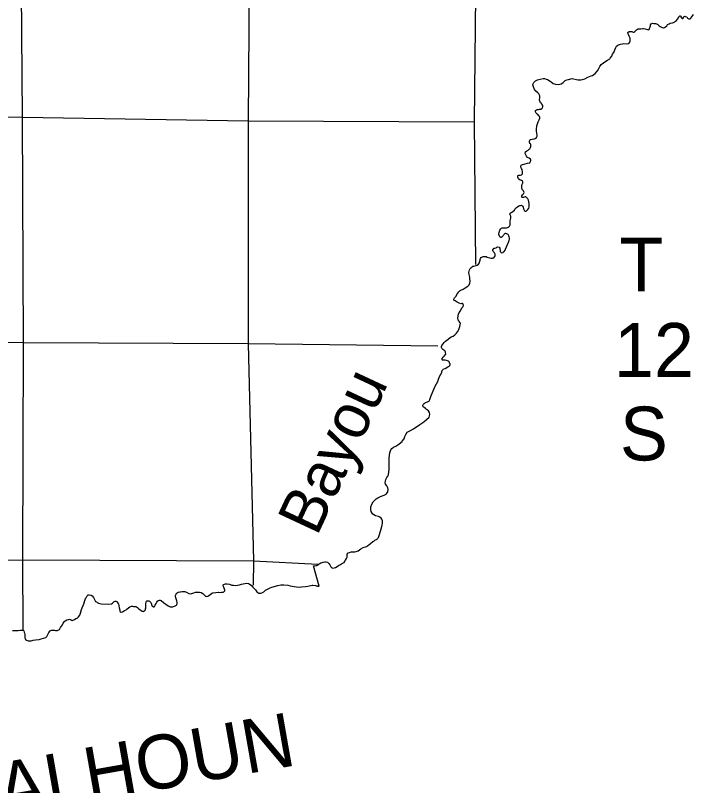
# Model space of a CAD drawing. Extents: x 369523 to 838377, y 495025 to 936819.
# Drawn here: x 707170 to 723147, y 607625 to 625753 of the extents above; entities that cross this region are included whole.
import ezdxf

# ---------------------------------------------------------------- set-up
doc = ezdxf.new("R2010")
doc.units = 0
for name, color, linetype in [('21', 7, 'Continuous'), ('Level 10', 7, 'Continuous'), ('Level 22', 7, 'Continuous'), ('Level 6', 7, 'Continuous')]:
    doc.layers.add(name, color=color, linetype=linetype)

msp = doc.modelspace()

# ---------------------------------------------------------------- linework, layer by layer
at = {"layer": '21'}
msp.add_line((721719, 617879), (721719, 617879), dxfattribs=at)
at = {"layer": 'Level 22'}
for points in [[(717984, 632258), (718036, 628459), (717975, 623251), (718009, 619890)], [(712679, 630326), (712692, 628709), (712656, 623272), (712654, 618019), (712776, 612916), (712771, 612344)], [(707356, 611282), (707347, 612941), (707357, 618044), (707336, 623361), (707299, 628330)], [(702444, 623403), (707336, 623361), (712656, 623272), (717975, 623251)], [(717123, 617969), (712654, 618019), (707357, 618044), (702484, 618099)], [(702445, 612932), (707347, 612941), (712776, 612916), (714295, 612837)]]:
    msp.add_lwpolyline(points, dxfattribs=at)
at = {"layer": 'Level 6'}
for points in [[(722357, 625490), (722405, 625469), (722427, 625458), (722435, 625458), (722465, 625467), (722484, 625484), (722515, 625507), (722534, 625536), (722570, 625557), (722595, 625568), (722603, 625568), (722649, 625581), (722672, 625586), (722690, 625595), (722708, 625603), (722723, 625614), (722743, 625631), (722770, 625662), (722795, 625696), (722800, 625719), (722809, 625735), (722813, 625739), (722819, 625743), (722825, 625743), (722833, 625742), (722845, 625734), (722850, 625720), (722864, 625697), (722881, 625679), (722891, 625681), (722901, 625686), (722916, 625708), (722927, 625725), (722937, 625733), (722945, 625731), (722984, 625717), (723006, 625691), (723019, 625682), (723033, 625674), (723051, 625671), (723055, 625671), (723063, 625675), (723078, 625690), (723109, 625717), (723132, 625751), (723147, 625778)], [(719602, 624265), (719636, 624267), (719677, 624251), (719709, 624243), (719770, 624207), (719790, 624186), (719842, 624152), (719890, 624132), (719954, 624126), (719999, 624135), (720025, 624145), (720063, 624169), (720093, 624193), (720124, 624220), (720160, 624240), (720190, 624246), (720202, 624248), (720284, 624267), (720419, 624237), (720461, 624234), (720491, 624236), (720531, 624244), (720581, 624262), (720658, 624303), (720692, 624313), (720736, 624327), (720762, 624339), (720831, 624388), (720881, 624448), (720918, 624507), (720940, 624553), (720967, 624599), (721023, 624637), (721081, 624676), (721118, 624698), (721170, 624732), (721182, 624746), (721217, 624795), (721231, 624821), (721237, 624839), (721257, 624871), (721272, 624893), (721292, 624945), (721312, 625001), (721327, 625030), (721359, 625050), (721377, 625060), (721425, 625074), (721473, 625082), (721504, 625089), (721570, 625085), (721620, 625093), (721646, 625124), (721652, 625150), (721655, 625182), (721649, 625218), (721629, 625268), (721611, 625304), (721599, 625334), (721596, 625354), (721628, 625374), (721648, 625378), (721690, 625374), (721720, 625358), (721742, 625360), (721760, 625377), (721780, 625393), (721805, 625411), (721827, 625433), (721845, 625441), (721861, 625441), (721873, 625441), (721907, 625441), (721945, 625444), (721967, 625442), (722009, 625436), (722059, 625418), (722091, 625417), (722102, 625419), (722112, 625443), (722130, 625509), (722134, 625535), (722147, 625557), (722161, 625565), (722181, 625569), (722209, 625565), (722241, 625566), (722253, 625564), (722271, 625556), (722287, 625550), (722297, 625544), (722311, 625534), (722337, 625506), (722357, 625490)], [(719059, 621878), (719027, 621902), (719019, 621910), (719007, 621944), (719003, 621966), (719007, 621982), (719015, 621984), (719029, 621992), (719049, 621996), (719069, 621994), (719090, 621997), (719118, 622021), (719120, 622039), (719116, 622067), (719106, 622125), (719093, 622147), (719075, 622181), (719075, 622199), (719085, 622227), (719115, 622243), (719157, 622255), (719182, 622263), (719236, 622274), (719270, 622280), (719292, 622284), (719308, 622314), (719310, 622334), (719309, 622346), (719303, 622366), (719277, 622390), (719247, 622404), (719231, 622410), (719207, 622440), (719191, 622470), (719179, 622504), (719186, 622540), (719218, 622562), (719248, 622582), (719276, 622602), (719286, 622615), (719307, 622647), (719313, 622669), (719315, 622689), (719315, 622711), (719307, 622727), (719291, 622737), (719281, 622775), (719281, 622791), (719286, 622817), (719308, 622833), (719380, 622847), (719388, 622847), (719412, 622854), (719447, 622878), (719463, 622908), (719465, 622936), (719453, 622980), (719448, 623026), (719448, 623076), (719456, 623154), (719475, 623222), (719489, 623251), (719510, 623295), (719526, 623331), (719522, 623357), (719516, 623373), (719504, 623393), (719484, 623415), (719464, 623431), (719440, 623449), (719423, 623483), (719423, 623487), (719425, 623513), (719449, 623529), (719467, 623537), (719491, 623539), (719515, 623543), (719551, 623549), (719580, 623566), (719590, 623586), (719594, 623600), (719592, 623632), (719572, 623662), (719560, 623678), (719542, 623697), (719532, 623721), (719517, 623761), (719527, 623820), (719521, 623860), (719504, 623904), (719480, 623931), (719428, 623973), (719400, 624009), (719374, 624073), (719359, 624119), (719369, 624141), (719385, 624175), (719426, 624217), (719466, 624236), (719532, 624250), (719602, 624265)], [(718709, 620621), (718691, 620614), (718681, 620602), (718673, 620590), (718663, 620570), (718649, 620556), (718634, 620542), (718622, 620534), (718614, 620528), (718602, 620526), (718580, 620544), (718574, 620554), (718572, 620560), (718561, 620594), (718557, 620610), (718567, 620640), (718585, 620700), (718604, 620726), (718622, 620744), (718636, 620752), (718664, 620752), (718684, 620753), (718724, 620753), (718740, 620755), (718764, 620761), (718784, 620767), (718809, 620789), (718827, 620826), (718829, 620920), (718832, 620950), (718834, 620950), (718842, 620978), (718844, 620996), (718844, 621010), (718840, 621024), (718832, 621042), (718822, 621060), (718819, 621080), (718825, 621102), (718849, 621116), (718867, 621124), (718899, 621144), (718925, 621171), (718934, 621189), (718940, 621199), (718974, 621231), (719000, 621251), (719026, 621269), (719051, 621277), (719067, 621282), (719089, 621284), (719109, 621274), (719123, 621260), (719133, 621236), (719142, 621204), (719154, 621172), (719164, 621156), (719178, 621142), (719206, 621148), (719222, 621162), (719245, 621188), (719263, 621215), (719271, 621247), (719271, 621271), (719271, 621293), (719270, 621323), (719266, 621369), (719258, 621401), (719244, 621433), (719216, 621461), (719198, 621485), (719180, 621482), (719158, 621474), (719142, 621466), (719130, 621464), (719118, 621464), (719106, 621466), (719100, 621478), (719098, 621484), (719098, 621492), (719104, 621504), (719120, 621530), (719145, 621558), (719147, 621570), (719153, 621582), (719151, 621602), (719139, 621624), (719121, 621640), (719111, 621654), (719100, 621694), (719098, 621742), (719108, 621784), (719118, 621796), (719126, 621803), (719128, 621819), (719125, 621829), (719123, 621839), (719113, 621853), (719095, 621868), (719071, 621876), (719059, 621878)], [(717719, 618905), (717723, 618929), (717721, 618939), (717715, 618957), (717701, 618969), (717689, 618970), (717665, 618968), (717625, 618982), (717581, 619006), (717557, 619016), (717529, 619032), (717509, 619044), (717499, 619057), (717497, 619067), (717503, 619086), (717513, 619102), (717525, 619116), (717552, 619148), (717572, 619184), (717592, 619214), (717613, 619248), (717645, 619275), (717661, 619285), (717715, 619311), (717768, 619343), (717832, 619380), (717858, 619410), (717877, 619450), (717885, 619500), (717879, 619554), (717872, 619592), (717858, 619656), (717854, 619702), (717857, 619730), (717867, 619765), (717883, 619793), (717901, 619815), (717919, 619831), (717948, 619847), (717968, 619853), (718026, 619864), (718052, 619872), (718076, 619896), (718101, 619930), (718107, 619944), (718117, 619990), (718119, 620008), (718125, 620028), (718142, 620053), (718170, 620069), (718186, 620075), (718214, 620075), (718238, 620077), (718264, 620077), (718286, 620061), (718340, 620050), (718378, 620040), (718408, 620036), (718428, 620044), (718444, 620048), (718463, 620076), (718473, 620099), (718473, 620131), (718457, 620167), (718427, 620196), (718414, 620222), (718416, 620232), (718438, 620267), (718448, 620273), (718462, 620273), (718466, 620273), (718492, 620285), (718510, 620299), (718528, 620309), (718565, 620299), (718582, 620277), (718582, 620259), (718590, 620221), (718590, 620211), (718594, 620199), (718604, 620183), (718616, 620171), (718630, 620168), (718662, 620176), (718672, 620188), (718682, 620200), (718706, 620228), (718717, 620254), (718790, 620417), (718796, 620429), (718804, 620455), (718808, 620485), (718809, 620513), (718803, 620545), (718797, 620565), (718787, 620579), (718775, 620593), (718747, 620609), (718735, 620615), (718723, 620621), (718709, 620621)], [(716081, 615587), (716130, 615613), (716182, 615647), (716212, 615668), (716285, 615726), (716285, 615730), (716325, 615788), (716344, 615843), (716366, 615891), (716401, 615941), (716481, 615984), (716548, 616024), (716699, 616121), (716792, 616190), (716856, 616238), (716915, 616300), (716935, 616361), (716923, 616409), (716898, 616443), (716852, 616478), (716828, 616500), (716796, 616522), (716780, 616540), (716770, 616566), (716770, 616578), (716776, 616598), (716790, 616612), (716800, 616620), (716805, 616622), (716833, 616640), (716881, 616659), (716927, 616685), (716933, 616709), (716954, 616787), (717009, 616918), (717060, 617024), (717121, 617135), (717139, 617191), (717172, 617267), (717194, 617303), (717213, 617354), (717225, 617394), (717247, 617420), (717257, 617432), (717294, 617446), (717356, 617479), (717392, 617497), (717408, 617515), (717412, 617539), (717411, 617551), (717395, 617569), (717393, 617593), (717375, 617613), (717351, 617625), (717327, 617631), (717293, 617640), (717271, 617640), (717249, 617640), (717231, 617642), (717223, 617650), (717221, 617664), (717225, 617680), (717245, 617710), (717273, 617732), (717310, 617781), (717310, 617783), (717300, 617829), (717294, 617851), (717272, 617871), (717260, 617877), (717240, 617890), (717224, 617902), (717214, 617918), (717213, 617924), (717207, 617938), (717209, 617960), (717217, 617984), (717245, 618023), (717272, 618053), (717300, 618089), (717433, 618190), (717483, 618206), (717526, 618235), (717562, 618271), (717588, 618305), (717619, 618361), (717643, 618431), (717652, 618508), (717640, 618528), (717624, 618550), (717614, 618564), (717604, 618581), (717598, 618599), (717596, 618625), (717597, 618684), (717605, 618720), (717625, 618762), (717652, 618800), (717686, 618870), (717711, 618893), (717719, 618905)], [(714254, 612330), (714276, 612326), (714290, 612320), (714310, 612318), (714324, 612316), (714191, 612794), (714217, 612800), (714247, 612802), (714269, 612804), (714301, 612823), (714324, 612841), (714364, 612865), (714396, 612877), (714420, 612885), (714458, 612894), (714487, 612894), (714525, 612880), (714552, 612856), (714574, 612820), (714592, 612788), (714604, 612772), (714616, 612756), (714650, 612745), (714676, 612747), (714708, 612761), (714747, 612781), (714783, 612803), (714827, 612832), (714877, 612858), (714912, 612876), (714940, 612913), (714950, 612931), (714968, 612967), (714983, 613001), (714985, 613059), (714989, 613073), (715009, 613103), (715042, 613115), (715082, 613126), (715124, 613128), (715164, 613124), (715198, 613136), (715244, 613149), (715273, 613171), (715307, 613199), (715363, 613227), (715416, 613246), (715446, 613256), (715468, 613270), (715502, 613300), (715532, 613324), (715591, 613367), (715613, 613381), (715639, 613399), (715696, 613426), (715700, 613438), (715722, 613464), (715738, 613510), (715771, 613610), (715786, 613672), (715814, 613755), (715819, 613799), (715819, 613857), (715805, 613895), (715787, 613921), (715757, 613941), (715723, 613958), (715655, 613978), (715615, 613996), (715587, 614014), (715575, 614034), (715552, 614078), (715544, 614118), (715546, 614190), (715565, 614250), (715601, 614306), (715618, 614328), (715670, 614377), (715706, 614401), (715753, 614421), (715809, 614446), (715855, 614462), (715901, 614484), (715928, 614514), (715940, 614540), (715948, 614591), (715943, 614633), (715921, 614677), (715891, 614722), (715879, 614760), (715885, 614792), (715898, 614829), (715924, 614873), (715946, 614907), (715959, 614941), (715972, 615069), (715979, 615336), (715988, 615458), (716015, 615530), (716041, 615558), (716081, 615587)], [(710819, 611831), (710875, 611830), (710931, 611852), (710965, 611872), (710982, 611900), (710984, 611924), (710974, 611970), (710958, 612020), (710946, 612048), (710941, 612080), (710943, 612100), (710957, 612132), (710961, 612140), (710979, 612163), (711007, 612177), (711044, 612185), (711062, 612187), (711100, 612193), (711142, 612194), (711162, 612192), (711178, 612188), (711202, 612176), (711256, 612146), (711258, 612146), (711294, 612140), (711330, 612149), (711370, 612163), (711413, 612175), (711445, 612181), (711477, 612180), (711507, 612180), (711549, 612166), (711587, 612146), (711601, 612132), (711629, 612102), (711645, 612082), (711655, 612082), (711673, 612079), (711705, 612083), (711727, 612103), (711761, 612125), (711792, 612147), (711812, 612163), (711892, 612172), (711954, 612174), (711974, 612172), (712022, 612175), (712061, 612181), (712079, 612185), (712091, 612193), (712105, 612209), (712105, 612227), (712097, 612251), (712083, 612293), (712068, 612323), (712066, 612351), (712082, 612361), (712092, 612367), (712120, 612371), (712160, 612374), (712210, 612364), (712272, 612342), (712306, 612339), (712365, 612337), (712399, 612343), (712451, 612351), (712495, 612362), (712577, 612384), (712618, 612390), (712658, 612383), (712676, 612375), (712734, 612333), (712767, 612297), (712791, 612267), (712823, 612229), (712839, 612207), (712859, 612188), (712881, 612170), (712905, 612156), (712929, 612152), (712953, 612156), (712975, 612162), (713025, 612188), (713058, 612223), (713173, 612277), (713213, 612292), (713353, 612335), (713422, 612349), (713494, 612349), (713584, 612340), (713646, 612330), (713738, 612313), (713793, 612303), (713857, 612299), (713907, 612302), (714005, 612314), (714059, 612321), (714164, 612341), (714178, 612343), (714242, 612336), (714254, 612330)], [(708508, 611507), (708524, 611516), (708544, 611524), (708562, 611534), (708594, 611554), (708624, 611566), (708655, 611594), (708689, 611639), (708707, 611683), (708730, 611771), (708783, 611904), (708816, 612008), (708832, 612046), (708842, 612062), (708863, 612094), (708887, 612112), (708901, 612115), (708911, 612115), (708955, 612109), (708979, 612093), (709011, 612049), (709023, 612021), (709060, 611961), (709080, 611947), (709100, 611933), (709126, 611922), (709192, 611904), (709367, 611893), (709433, 611905), (709457, 611917), (709473, 611936), (709494, 611956), (709518, 611964), (709536, 611962), (709558, 611956), (709570, 611944), (709586, 611922), (709595, 611900), (709607, 611856), (709613, 611810), (709619, 611786), (709623, 611774), (709627, 611752), (709632, 611732), (709638, 611714), (709654, 611706), (709664, 611704), (709690, 611715), (709739, 611743), (709777, 611763), (709805, 611787), (709868, 611836), (709908, 611846), (709928, 611846), (709954, 611844), (709978, 611842), (710008, 611839), (710026, 611833), (710046, 611815), (710076, 611789), (710110, 611765), (710160, 611733), (710176, 611727), (710194, 611725), (710212, 611738), (710220, 611746), (710234, 611764), (710237, 611784), (710239, 611810), (710239, 611852), (710239, 611882), (710245, 611914), (710250, 611942), (710258, 611964), (710270, 611972), (710282, 611976), (710316, 611973), (710330, 611963), (710358, 611937), (710366, 611915), (710382, 611861), (710389, 611845), (710407, 611839), (710413, 611835), (710431, 611831), (710440, 611835), (710454, 611853), (710464, 611871), (710484, 611909), (710500, 611944), (710519, 611968), (710537, 611980), (710549, 611984), (710565, 611988), (710583, 611988), (710601, 611982), (710655, 611934), (710687, 611913), (710715, 611895), (710769, 611855), (710819, 611831)], [(707104, 611273), (707176, 611277), (707220, 611278), (707238, 611276), (707285, 611280), (707307, 611284), (707331, 611284), (707349, 611284), (707369, 611269), (707379, 611239), (707384, 611219), (707390, 611173), (707390, 611140), (707394, 611104), (707400, 611086), (707411, 611064), (707427, 611045), (707435, 611045), (707471, 611035), (707538, 611033), (707592, 611046), (707644, 611052), (707730, 611066), (707777, 611077), (707835, 611091), (707887, 611109), (707909, 611135), (707924, 611166), (707960, 611232), (707986, 611268), (708019, 611284), (708041, 611284), (708057, 611287), (708089, 611283), (708113, 611279), (708139, 611273), (708151, 611275), (708167, 611283), (708191, 611289), (708205, 611297), (708236, 611346), (708278, 611410), (708297, 611446), (708323, 611484), (708343, 611504), (708385, 611523), (708418, 611531), (708442, 611539), (708460, 611535), (708482, 611523), (708508, 611507)]]:
    msp.add_lwpolyline(points, dxfattribs=at)

# ---------------------------------------------------------------- texts
at = {"layer": '21'}
for s, height, p in [('T', 1267, (721396, 619257)), ('12', 1267.2, (721270, 617246)), ('S', 1267, (721411, 615278))]:
    msp.add_text(s, height=height, dxfattribs=at).set_placement(p)
msp.add_text('CALHOUN', height=1267.2, rotation=10, dxfattribs=at).set_placement((705660, 606670))
at = {"layer": 'Level 10'}
msp.add_text('Bayou', height=1056, rotation=65, dxfattribs=at).set_placement((714272, 613473))

doc.saveas('drawing.dxf')
